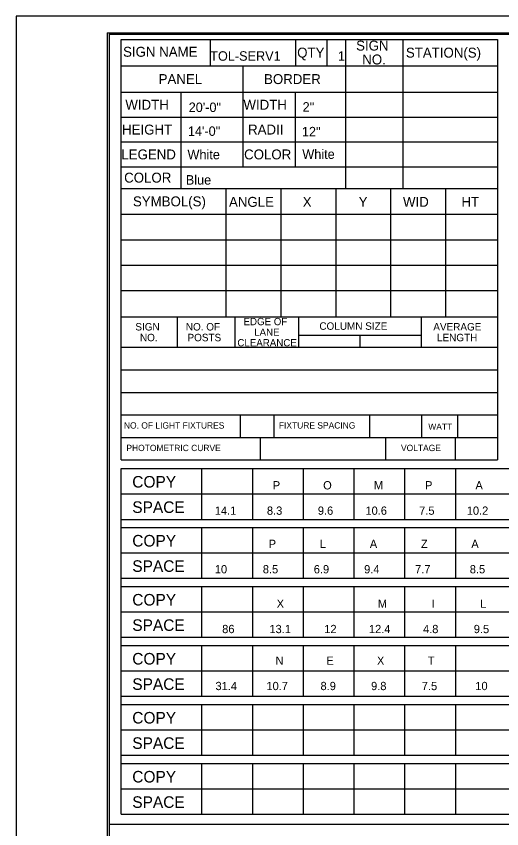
# Model space of a CAD drawing. Extents: x 17890484 to 17890754, y 17897495 to 17897992.
# Drawn here: x 17890483.9 to 17890512.7, y 17897550.71 to 17897598.87 of the extents above; entities that cross this region are included whole.
import ezdxf

# ---------------------------------------------------------------- set-up
doc = ezdxf.new("R2010")
doc.units = 0
for name, color, linetype in [('GSSign', 7, 'Continuous'), ('PlotBorder_dp', 7, 'Continuous'), ('SheetBorder_dp', 7, 'Continuous'), ('SheetLinesMisc1_dp', 7, 'Continuous'), ('SheetLinesMisc2_dp', 7, 'Continuous'), ('TextMinor', 7, 'Continuous')]:
    doc.layers.add(name, color=color, linetype=linetype)

msp = doc.modelspace()

# ---------------------------------------------------------------- linework, layer by layer
at = {"layer": 'PlotBorder_dp'}
msp.add_lwpolyline([(17890483.9, 17897494.956), (17890645.649, 17897494.956), (17890645.649, 17897598.868), (17890483.9, 17897598.868)], close=True, dxfattribs=at)
at = {"layer": 'SheetBorder_dp'}
for q in [(17890489.292, 17897495.936), (17890640.258, 17897597.887)]:
    msp.add_line((17890489.292, 17897597.887), q, dxfattribs=at)
at = {"layer": 'SheetLinesMisc1_dp'}
for p, q in [((17890495.428, 17897595.928), (17890495.428, 17897597.496)), ((17890500.475, 17897597.496), (17890500.475, 17897595.928)), ((17890502.328, 17897597.496), (17890502.328, 17897595.928)), ((17890503.432, 17897597.496), (17890503.432, 17897588.662)), ((17890506.827, 17897597.496), (17890506.827, 17897588.662)), ((17890490.134, 17897595.928), (17890512.445, 17897595.928)), ((17890497.345, 17897595.928), (17890497.345, 17897589.926)), ((17890490.134, 17897594.359), (17890512.445, 17897594.359)), ((17890493.66, 17897594.359), (17890493.66, 17897588.662)), ((17890500.456, 17897594.344), (17890500.456, 17897589.926)), ((17890490.134, 17897592.887), (17890512.445, 17897592.887)), ((17890490.134, 17897591.415), (17890512.445, 17897591.415)), ((17890490.134, 17897589.942), (17890512.445, 17897589.942)), ((17890490.134, 17897588.662), (17890512.445, 17897588.662)), ((17890496.33, 17897588.662), (17890496.33, 17897581.043)), ((17890499.59, 17897588.662), (17890499.59, 17897581.043)), ((17890502.85, 17897588.662), (17890502.85, 17897581.043)), ((17890506.11, 17897588.633), (17890506.11, 17897581.043)), ((17890509.37, 17897588.633), (17890509.37, 17897581.043)), ((17890490.139, 17897587.129), (17890512.445, 17897587.129)), ((17890490.139, 17897585.625), (17890512.445, 17897585.625)), ((17890490.139, 17897584.122), (17890512.445, 17897584.122)), ((17890490.139, 17897582.619), (17890512.445, 17897582.619)), ((17890490.134, 17897581.043), (17890512.445, 17897581.043)), ((17890493.445, 17897581.043), (17890493.445, 17897579.246)), ((17890496.867, 17897581.043), (17890496.867, 17897579.246)), ((17890500.645, 17897581.043), (17890500.645, 17897579.246)), ((17890507.921, 17897581.043), (17890507.921, 17897579.246)), ((17890500.645, 17897579.965), (17890507.916, 17897579.965)), ((17890504.281, 17897579.965), (17890504.281, 17897579.246)), ((17890490.134, 17897579.246), (17890512.445, 17897579.246)), ((17890490.134, 17897577.911), (17890512.445, 17897577.911)), ((17890490.134, 17897576.575), (17890512.445, 17897576.575)), ((17890490.134, 17897575.24), (17890512.445, 17897575.24)), ((17890490.134, 17897573.904), (17890512.445, 17897573.904))]:
    msp.add_line(p, q, dxfattribs=at)
at = {"layer": 'SheetLinesMisc2_dp'}
for p, q in [((17890489.413, 17897597.808), (17890639.869, 17897597.808)), ((17890489.413, 17897597.808), (17890489.413, 17897504.15)), ((17890490.134, 17897572.568), (17890490.134, 17897597.496)), ((17890490.134, 17897597.496), (17890512.445, 17897597.496)), ((17890512.445, 17897597.496), (17890512.445, 17897572.568)), ((17890490.134, 17897575.239), (17890512.44, 17897575.239)), ((17890497.192, 17897575.239), (17890497.192, 17897573.904)), ((17890499.185, 17897575.239), (17890499.185, 17897573.904)), ((17890504.86, 17897575.239), (17890504.86, 17897573.904)), ((17890507.947, 17897575.239), (17890507.947, 17897573.904)), ((17890510.076, 17897575.239), (17890510.076, 17897573.904)), ((17890490.134, 17897573.904), (17890512.44, 17897573.904)), ((17890498.362, 17897573.904), (17890498.362, 17897572.568)), ((17890505.805, 17897573.904), (17890505.805, 17897572.568)), ((17890509.947, 17897573.904), (17890509.947, 17897572.568)), ((17890490.134, 17897572.568), (17890512.44, 17897572.568)), ((17890490.134, 17897572.568), (17890512.445, 17897572.568)), ((17890490.134, 17897572.057), (17890564.13, 17897572.057)), ((17890490.134, 17897551.569), (17890490.134, 17897572.057)), ((17890494.897, 17897572.057), (17890494.897, 17897569.05)), ((17890497.908, 17897572.057), (17890497.908, 17897569.05)), ((17890500.918, 17897572.057), (17890500.918, 17897569.05)), ((17890503.928, 17897572.057), (17890503.928, 17897569.05)), ((17890506.938, 17897572.057), (17890506.938, 17897569.05)), ((17890509.948, 17897572.057), (17890509.948, 17897569.05)), ((17890490.134, 17897570.554), (17890564.13, 17897570.554)), ((17890490.134, 17897569.05), (17890564.13, 17897569.05)), ((17890490.134, 17897568.56), (17890564.13, 17897568.56)), ((17890494.897, 17897568.56), (17890494.897, 17897565.555)), ((17890497.908, 17897568.56), (17890497.908, 17897565.555)), ((17890500.918, 17897568.56), (17890500.918, 17897565.555)), ((17890503.928, 17897568.56), (17890503.928, 17897565.555)), ((17890506.938, 17897568.56), (17890506.938, 17897565.555)), ((17890509.948, 17897568.56), (17890509.948, 17897565.555)), ((17890490.134, 17897567.057), (17890564.13, 17897567.058)), ((17890490.134, 17897565.555), (17890564.13, 17897565.555)), ((17890490.134, 17897565.064), (17890564.13, 17897565.064)), ((17890494.897, 17897565.064), (17890494.897, 17897562.058)), ((17890497.908, 17897565.064), (17890497.908, 17897562.058)), ((17890500.918, 17897565.064), (17890500.918, 17897562.058)), ((17890503.928, 17897565.064), (17890503.928, 17897562.058)), ((17890506.938, 17897565.064), (17890506.938, 17897562.058)), ((17890509.948, 17897565.064), (17890509.948, 17897562.058)), ((17890490.134, 17897563.561), (17890564.13, 17897563.561)), ((17890490.134, 17897562.058), (17890564.13, 17897562.058)), ((17890490.134, 17897561.568), (17890564.13, 17897561.568)), ((17890494.897, 17897561.568), (17890494.897, 17897558.562)), ((17890497.908, 17897561.568), (17890497.908, 17897558.562)), ((17890500.918, 17897561.568), (17890500.918, 17897558.562)), ((17890503.928, 17897561.568), (17890503.928, 17897558.562)), ((17890506.938, 17897561.568), (17890506.938, 17897558.562)), ((17890509.948, 17897561.568), (17890509.948, 17897558.562)), ((17890490.134, 17897560.065), (17890564.13, 17897560.065)), ((17890490.134, 17897558.562), (17890564.13, 17897558.562)), ((17890490.134, 17897558.071), (17890564.13, 17897558.071)), ((17890494.897, 17897558.071), (17890494.897, 17897555.065)), ((17890497.908, 17897558.071), (17890497.908, 17897555.065)), ((17890500.918, 17897558.071), (17890500.918, 17897555.065)), ((17890503.928, 17897558.071), (17890503.928, 17897555.065)), ((17890506.938, 17897558.071), (17890506.938, 17897555.065)), ((17890509.948, 17897558.071), (17890509.948, 17897555.065)), ((17890490.134, 17897556.569), (17890564.13, 17897556.569)), ((17890490.134, 17897555.065), (17890564.13, 17897555.065)), ((17890490.134, 17897554.575), (17890564.13, 17897554.575)), ((17890494.897, 17897554.575), (17890494.897, 17897551.569)), ((17890497.908, 17897554.575), (17890497.908, 17897551.569)), ((17890500.918, 17897554.575), (17890500.918, 17897551.569)), ((17890503.928, 17897554.575), (17890503.928, 17897551.569)), ((17890506.938, 17897554.575), (17890506.938, 17897551.569)), ((17890509.948, 17897554.575), (17890509.948, 17897551.569)), ((17890490.134, 17897553.073), (17890564.13, 17897553.073)), ((17890490.134, 17897551.569), (17890564.13, 17897551.569)), ((17890489.413, 17897550.979), (17890564.641, 17897550.979))]:
    msp.add_line(p, q, dxfattribs=at)

# ---------------------------------------------------------------- texts
at = {"layer": 'GSSign'}
for s, height, p in [('TOL-SERV1', 0.5624, (17890495.407, 17897596.231)), ('1', 0.562, (17890502.98, 17897596.23)), ('20\'-0"', 0.5624, (17890494.131, 17897593.191)), ('2"', 0.5624, (17890500.888, 17897593.212)), ('14\'-0"', 0.5624, (17890494.083, 17897591.778)), ('12"', 0.5624, (17890500.845, 17897591.747)), ('White', 0.5624, (17890494.058, 17897590.391)), ('White', 0.5624, (17890500.87, 17897590.413)), ('Blue', 0.5624, (17890493.959, 17897588.888)), ('O', 0.49, (17890502.108, 17897570.823)), ('P', 0.49, (17890499.121, 17897570.823)), ('M', 0.49, (17890505.118, 17897570.823)), ('P', 0.49, (17890508.152, 17897570.823)), ('A', 0.49, (17890511.139, 17897570.823)), ('14.1', 0.4902, (17890495.679, 17897569.32)), ('8.3', 0.4902, (17890498.771, 17897569.32)), ('9.6', 0.4902, (17890501.793, 17897569.32)), ('10.6', 0.4902, (17890504.616, 17897569.32)), ('7.5', 0.4902, (17890507.802, 17897569.32)), ('10.2', 0.4902, (17890510.626, 17897569.32)), ('P', 0.49, (17890498.878, 17897567.351)), ('L', 0.49, (17890501.912, 17897567.351)), ('A', 0.49, (17890504.875, 17897567.351)), ('Z', 0.49, (17890507.909, 17897567.351)), ('A', 0.49, (17890510.896, 17897567.351)), ('10', 0.4902, (17890495.681, 17897565.848)), ('8.5', 0.4902, (17890498.528, 17897565.848)), ('6.9', 0.4902, (17890501.55, 17897565.848)), ('9.4', 0.4902, (17890504.537, 17897565.848)), ('7.7', 0.4902, (17890507.559, 17897565.848)), ('8.5', 0.4902, (17890510.805, 17897565.848)), ('X', 0.49, (17890499.35, 17897563.807)), ('M', 0.49, (17890505.348, 17897563.807)), ('I', 0.49, (17890508.545, 17897563.807)), ('L', 0.49, (17890511.415, 17897563.807)), ('86', 0.4902, (17890496.118, 17897562.304)), ('13.1', 0.4902, (17890498.919, 17897562.304)), ('12', 0.4902, (17890502.174, 17897562.304)), ('12.4', 0.4902, (17890504.823, 17897562.304)), ('4.8', 0.4902, (17890508.031, 17897562.304)), ('9.5', 0.4902, (17890511.042, 17897562.304)), ('N', 0.49, (17890499.279, 17897560.43)), ('E', 0.49, (17890502.301, 17897560.43)), ('X', 0.49, (17890505.299, 17897560.43)), ('T', 0.49, (17890508.31, 17897560.43)), ('31.4', 0.4902, (17890495.72, 17897558.927)), ('10.7', 0.4902, (17890498.742, 17897558.927)), ('8.9', 0.4902, (17890501.95, 17897558.927)), ('9.8', 0.4902, (17890504.949, 17897558.927)), ('7.5', 0.4902, (17890507.96, 17897558.927)), ('10', 0.4902, (17890511.133, 17897558.927))]:
    msp.add_text(s, height=height, dxfattribs=at).set_placement(p)
at = {"layer": 'TextMinor'}
for s, height, p in [('SIGN', 0.5882, (17890504.063, 17897596.835)), ('SIGN NAME', 0.5882, (17890490.238, 17897596.467)), ('QTY', 0.5882, (17890500.566, 17897596.418)), ('STATION(S)', 0.5882, (17890507.016, 17897596.418)), ('NO.', 0.5882, (17890504.426, 17897596.012)), ('PANEL', 0.5882, (17890492.348, 17897594.849)), ('BORDER', 0.5882, (17890498.601, 17897594.849)), ('WIDTH', 0.5882, (17890490.374, 17897593.329)), ('WIDTH', 0.5882, (17890497.378, 17897593.329)), ('HEIGHT', 0.5882, (17890490.178, 17897591.857)), ('RADII', 0.5882, (17890497.653, 17897591.857)), ('LEGEND', 0.5882, (17890490.136, 17897590.384)), ('COLOR', 0.5882, (17890497.418, 17897590.384)), ('COLOR', 0.5882, (17890490.303, 17897589.008)), ('SYMBOL(S)', 0.5882, (17890490.824, 17897587.601)), ('ANGLE', 0.5882, (17890496.52, 17897587.572)), ('X', 0.588, (17890500.895, 17897587.572)), ('Y', 0.588, (17890504.215, 17897587.572)), ('WID', 0.5882, (17890506.842, 17897587.572)), ('HT', 0.5882, (17890510.308, 17897587.572)), ('EDGE OF', 0.4313, (17890497.382, 17897580.556)), ('SIGN', 0.4411, (17890490.967, 17897580.243)), ('NO. OF', 0.4411, (17890493.96, 17897580.243)), ('COLUMN SIZE', 0.44113, (17890501.883, 17897580.284)), ('AVERAGE', 0.4411, (17890508.641, 17897580.243)), ('NO.', 0.4411, (17890491.24, 17897579.605)), ('POSTS', 0.4411, (17890494.059, 17897579.605)), ('LANE', 0.4313, (17890498.015, 17897579.929)), ('LENGTH', 0.4411, (17890508.858, 17897579.605)), ('CLEARANCE', 0.4313, (17890497.019, 17897579.302)), ('NO. OF LIGHT FIXTURES', 0.37485, (17890490.288, 17897574.429)), ('FIXTURE SPACING', 0.37485, (17890499.479, 17897574.429)), ('WATT', 0.3749, (17890508.344, 17897574.355)), ('PHOTOMETRIC CURVE', 0.37485, (17890490.435, 17897573.094)), ('VOLTAGE', 0.3749, (17890506.724, 17897573.094)), ('COPY', 0.6862, (17890490.783, 17897570.932)), ('SPACE', 0.6862, (17890490.783, 17897569.429)), ('COPY', 0.6862, (17890490.783, 17897567.439)), ('SPACE', 0.6862, (17890490.783, 17897565.936)), ('COPY', 0.6862, (17890490.783, 17897563.94)), ('SPACE', 0.6862, (17890490.783, 17897562.437)), ('COPY', 0.6862, (17890490.783, 17897560.444)), ('SPACE', 0.6862, (17890490.783, 17897558.941)), ('COPY', 0.6862, (17890490.783, 17897556.947)), ('SPACE', 0.6862, (17890490.783, 17897555.444)), ('COPY', 0.6862, (17890490.783, 17897553.452)), ('SPACE', 0.6862, (17890490.783, 17897551.948))]:
    msp.add_text(s, height=height, dxfattribs=at).set_placement(p)

doc.saveas('drawing.dxf')
